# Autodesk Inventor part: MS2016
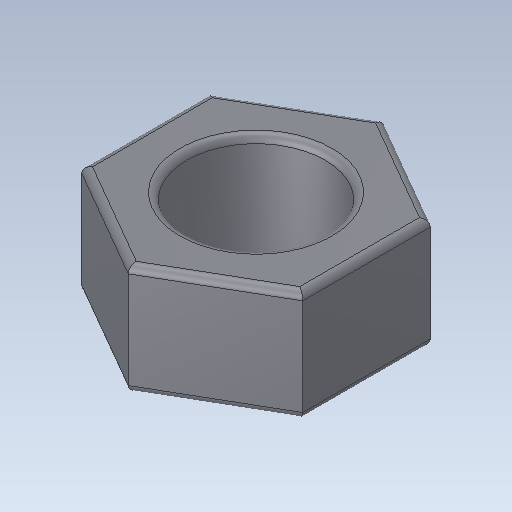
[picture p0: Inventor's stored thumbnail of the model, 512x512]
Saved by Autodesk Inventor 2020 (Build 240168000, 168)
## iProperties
Created: 2015-11
Part Number: MS2016
Material: Ogólny
Document SubType Name: Modeling
Designer: Tomasz
Density: 1 g/cm^3
Appearance: Domyślna
Sending System: SolidWorks 2017
Last Author: Tomasz
Last Saved: 2017-09-17
Author: Tomasz
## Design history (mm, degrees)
feature "Imported1"
node "Bryła1"
